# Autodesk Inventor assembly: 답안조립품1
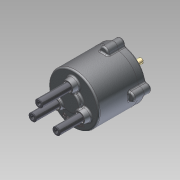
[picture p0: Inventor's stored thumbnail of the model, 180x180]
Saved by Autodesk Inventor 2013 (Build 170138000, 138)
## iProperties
Created: 2014-12
Part Number: 답안조립품1
Document SubType Name: Assembly
Designer: hanacad19
Author: hanacad19
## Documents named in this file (14)
- C:\Documents and Settings\hanacad19\바탕 화면\Inventor1급-김현\답안조립품1.iam
- C:\Documents and Settings\hanacad19\바탕 화면\Inventor1급-김현\몸체.ipt
- C:\Documents and Settings\hanacad19\바탕 화면\Inventor1급-김현\커버.ipt
- C:\Documents and Settings\hanacad19\바탕 화면\Inventor1급-김현\오일실.ipt
- C:\Documents and Settings\hanacad19\바탕 화면\Inventor1급-김현\M5x0.5x20.ipt
- C:\Documents and Settings\hanacad19\바탕 화면\Inventor1급-김현\베어링 NA 4900.ipt
- C:\Documents and Settings\hanacad19\바탕 화면\Inventor1급-김현\메인 축.ipt
- C:\Documents and Settings\hanacad19\바탕 화면\Inventor1급-김현\멈춤링 22 x 1.2.ipt
- C:\Documents and Settings\hanacad19\바탕 화면\Inventor1급-김현\판캠.ipt
- C:\Documents and Settings\hanacad19\바탕 화면\Inventor1급-김현\슬라이드 축.ipt
- C:\Documents and Settings\hanacad19\바탕 화면\Inventor1급-김현\가변스프링-01.ipt
- C:\Documents and Settings\hanacad19\바탕 화면\Inventor1급-김현\가변스프링-02.ipt
- C:\Documents and Settings\hanacad19\바탕 화면\Inventor1급-김현\가변스프링-03.ipt
- C:\Documents and Settings\hanacad19\바탕 화면\Inventor1급-김현\멈춤링 10 x 1.ipt
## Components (7 placed, 4 different names)
1. 가변스프링-01:1
2. 가변스프링-02:1
3. 가변스프링-03:1
4. M5x0.5x20:1
5. M5x0.5x20:2
6. M5x0.5x20:3
7. M5x0.5x20:4
